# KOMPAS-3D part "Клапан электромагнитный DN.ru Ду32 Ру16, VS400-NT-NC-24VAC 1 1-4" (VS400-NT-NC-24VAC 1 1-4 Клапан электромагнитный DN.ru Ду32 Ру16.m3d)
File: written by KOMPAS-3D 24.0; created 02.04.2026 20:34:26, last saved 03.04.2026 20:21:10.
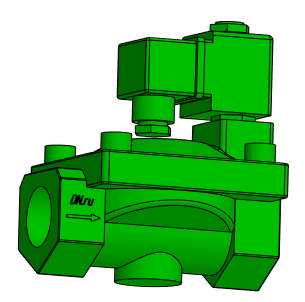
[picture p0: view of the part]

Document properties: Автор: artio; Полное имя файла: C:\Users\artio\OneDrive\Рабочий стол\Клапан электромагнитный DN.ru\VS400-NT-NC\VS400-NT-NC-24VAC 1 1-4 Клапан электромагнитный DN.ru Ду32 Ру16.m3d

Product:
- Body: Тело 1  | qty 1
    Масса: 4.144257
- Part/product: Клапан электромагнитный DN.ru Ду32 Ру16  | designation VS400-NT-NC-24VAC 1 1-4
    Масса: 2.569
    Раздел спецификации: Прочие изделия
    Примечание: D130-05495
    additional columns: ef56311e-7521-43dc-8291-0e6108b3d81d; VS400-ET-NC-220VAC 1 1-4; artio; c; Шероховатость не задана; Да

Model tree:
1. Операция без истории:1

Expressions: VS400-NT-NC-24VAC 1 1-4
